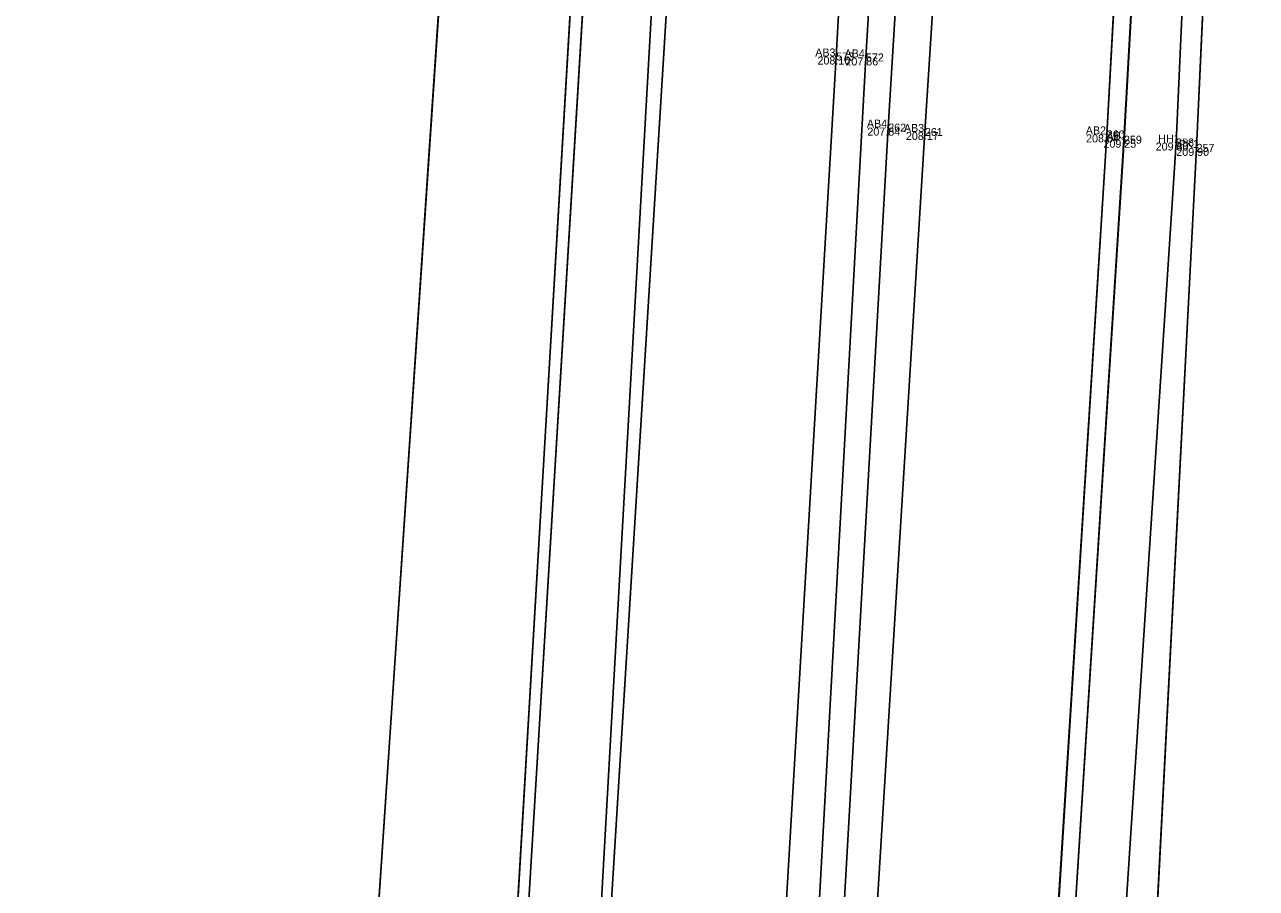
# Model space of a CAD drawing. Extents: x -263091 to -262565, y -1238731 to -1237092.
# Drawn here: x -262850.07 to -262819.29, y -1237979.18 to -1237957.59 of the extents above; entities that cross this region are included whole.
import ezdxf

# ---------------------------------------------------------------- set-up
doc = ezdxf.new("R2010")
doc.units = 0
for name, color, linetype in [('01_Hrana_betónu', 7, 'Continuous'), ('02_Oplotenie', 7, 'Continuous'), ('03_Asfalt', 7, 'Continuous'), ('05_Hrana_terénu', 7, 'Continuous'), ('09_Múrik', 7, 'Continuous'), ('Groma (21)', 7, 'Continuous'), ('Groma (22)', 7, 'Continuous'), ('Groma (23)', 7, 'Continuous'), ('Groma (24)', 7, 'Continuous'), ('U003_Asfalt', 7, 'Continuous'), ('U003_Betónové_múriky', 7, 'Continuous'), ('U003_Betónové_panely', 7, 'Continuous'), ('U003_Zeleň_mimo', 7, 'Continuous'), ('U003_Zeleň_vnútro', 7, 'Continuous'), ('U003_Zeleň_zatrávňovač', 7, 'Continuous'), ('U005_Betóny_prídavné', 7, 'Continuous')]:
    doc.layers.add(name, color=color, linetype=linetype)

msp = doc.modelspace()

# ---------------------------------------------------------------- linework, layer by layer
at = {"layer": '01_Hrana_betónu'}
for points in [[(-262903.088, -1238238.797), (-262890.817, -1238204.479), (-262885.468, -1238189.492), (-262878.003, -1238168.56), (-262870.455, -1238147.513), (-262864.947, -1238132.168), (-262859.037, -1238116.651), (-262848.977, -1238095.826), (-262842.353, -1238078.361), (-262839.446, -1238067.823), (-262836.783, -1238055.069), (-262834.905, -1238040.999), (-262833.763, -1238025.462), (-262832.297, -1238000.555), (-262831.13, -1237981.111), (-262829.791, -1237958.391), (-262828.651, -1237937.03), (-262828.571, -1237935.876)], [(-262827.762, -1237935.927), (-262827.853, -1237937.062), (-262829.049, -1237958.415), (-262830.305, -1237981.211), (-262831.433, -1238000.629), (-262832.987, -1238025.43), (-262834.086, -1238041.027), (-262836.169, -1238055.023), (-262838.684, -1238068.024), (-262841.681, -1238078.569), (-262848.285, -1238096.308), (-262858.162, -1238116.913), (-262863.876, -1238132.122), (-262869.919, -1238147.692), (-262877.244, -1238168.638), (-262884.69, -1238189.67), (-262901.991, -1238238.762)], [(-262827.034, -1237935.973), (-262827.072, -1237937.036), (-262828.491, -1237960.168), (-262829.643, -1237980.454), (-262830.754, -1238002.123), (-262832.4, -1238026.024), (-262833.369, -1238041.644), (-262835.263, -1238055.011), (-262838.048, -1238068.261), (-262841.826, -1238081.232), (-262846.645, -1238094.136), (-262857.777, -1238117.273), (-262863.292, -1238131.948), (-262884.082, -1238190.299), (-262901.352, -1238238.742)], [(-262900.376, -1238238.711), (-262890.192, -1238209.46), (-262883.463, -1238190.564), (-262868.512, -1238148.877), (-262862.514, -1238132.276), (-262857.014, -1238117.706), (-262845.846, -1238094.561), (-262841.058, -1238081.49), (-262837.218, -1238068.474), (-262834.492, -1238055.416), (-262832.606, -1238041.772), (-262831.509, -1238026.143), (-262830.024, -1238002.24), (-262828.826, -1237980.518), (-262827.576, -1237960.277), (-262826.117, -1237937.218), (-262826.079, -1237936.033)]]:
    msp.add_lwpolyline(points, dxfattribs=at)
at = {"layer": '02_Oplotenie'}
for points in [[(-262912.451, -1238238.295), (-262908.254, -1238226.663), (-262901.526, -1238207.942), (-262898.552, -1238199.602), (-262894.22, -1238186.327), (-262886.794, -1238165.648), (-262879.297, -1238144.201), (-262873.976, -1238128.814), (-262867.141, -1238113.572), (-262855.316, -1238089.931), (-262850.675, -1238078.807), (-262846.261, -1238065.654), (-262843.56, -1238054.226), (-262842.344, -1238048.099), (-262841.445, -1238040.349), (-262840.733, -1238030.077), (-262839.013, -1238000.384), (-262838.353, -1237989.712), (-262835.178, -1237935.879)], [(-262819.762, -1237938.034), (-262820.788, -1237960.675), (-262821.837, -1237980.919), (-262823.308, -1238002.106), (-262824.582, -1238026.068), (-262825.82, -1238041.973), (-262827.772, -1238056.552), (-262830.57, -1238069.546), (-262834.589, -1238083.855), (-262839.328, -1238095.835), (-262848.782, -1238120.942), (-262853.684, -1238135.175), (-262859.896, -1238152.781), (-262867.698, -1238174.329), (-262874.833, -1238193.487), (-262881.88, -1238212.036), (-262887.174, -1238225.693), (-262888.829, -1238230.138)]]:
    msp.add_lwpolyline(points, dxfattribs=at)
at = {"layer": '03_Asfalt'}
msp.add_lwpolyline([(-262912.678, -1238239.103), (-262913.356, -1238239.285), (-262915.717, -1238239.279), (-262916.328, -1238238.784), (-262916.575, -1238236.319), (-262915.768, -1238233.661), (-262912.404, -1238225.097), (-262904.805, -1238205.606), (-262896.687, -1238184.948), (-262888.478, -1238163.929), (-262880.124, -1238142.63), (-262874.65, -1238128.675), (-262868.549, -1238113.075), (-262858.861, -1238088.481), (-262853.132, -1238074.038), (-262850.084, -1238066.288), (-262845.869, -1238049.471), (-262845.094, -1238038.662), (-262844.346, -1238028.542), (-262842.599, -1238000.955), (-262841.603, -1237985.168), (-262838.824, -1237943.888), (-262838.24, -1237934.633), (-262838.283, -1237933.488)], dxfattribs=at)
at = {"layer": '05_Hrana_terénu'}
for points in [[(-262835.062, -1237935.275), (-262834.86, -1237936.333), (-262838.087, -1237989.633), (-262838.484, -1238000.332), (-262840.387, -1238030.181), (-262840.991, -1238040.253), (-262843.126, -1238054.282), (-262845.675, -1238066.436), (-262850.413, -1238079.623), (-262854.798, -1238090.209), (-262863.856, -1238108.78), (-262866.643, -1238114.502), (-262872.333, -1238129.41), (-262877.981, -1238144.625), (-262885.616, -1238166.033), (-262893.121, -1238186.676), (-262898.244, -1238201.149), (-262900.554, -1238208.001), (-262907.375, -1238226.781), (-262911.85, -1238238.364), (-262912.678, -1238239.103)], [(-262849.564, -1238120.544), (-262839.894, -1238095.583), (-262835.301, -1238083.403), (-262831.402, -1238069.334), (-262828.632, -1238056.516), (-262826.436, -1238041.83), (-262825.08, -1238026.06), (-262823.863, -1238001.967), (-262822.633, -1237980.847), (-262821.298, -1237960.54), (-262820.334, -1237939.047), (-262819.871, -1237937.657)]]:
    msp.add_lwpolyline(points, dxfattribs=at)
at = {"layer": '09_Múrik'}
for points in [[(-262845.277, -1238070.627), (-262844.218, -1238066.744), (-262841.577, -1238054.272), (-262839.647, -1238040.289), (-262838.75, -1238030.675), (-262836.979, -1238000.411), (-262836.237, -1237989.843), (-262834.391, -1237956.949), (-262833.055, -1237935.594)], [(-262844.833, -1238070.767), (-262843.906, -1238066.814), (-262841.249, -1238054.245), (-262839.306, -1238040.158), (-262838.493, -1238030.433), (-262836.614, -1238000.277), (-262836.049, -1237989.856), (-262833.996, -1237956.678), (-262832.67, -1237935.618)], [(-262840.924, -1238094.827), (-262836.941, -1238083.068), (-262832.969, -1238069.042), (-262830.214, -1238056.416), (-262828.063, -1238041.942), (-262826.83, -1238026.465), (-262825.494, -1238001.855), (-262824.316, -1237980.84), (-262823.031, -1237960.337), (-262821.719, -1237936.336)], [(-262840.6, -1238094.732), (-262836.43, -1238082.967), (-262832.633, -1238069.1), (-262829.86, -1238056.421), (-262827.688, -1238042.018), (-262826.338, -1238026.448), (-262825.108, -1238001.872), (-262823.89, -1237980.741), (-262822.602, -1237960.47), (-262821.253, -1237936.39)]]:
    msp.add_lwpolyline(points, dxfattribs=at)
at = {"layer": 'Groma (21)'}
for centre in [(-262829.791, -1237958.391), (-262829.049, -1237958.415), (-262828.491, -1237960.168), (-262827.576, -1237960.277), (-262823.031, -1237960.337), (-262822.602, -1237960.47), (-262821.298, -1237960.54), (-262820.788, -1237960.675)]:
    msp.add_circle(centre, 0.01, dxfattribs=at)
at = {"layer": 'U003_Asfalt'}
for points in [[(-262836.86, -1238089.78), (-262834.59, -1238083.86), (-262830.57, -1238069.55), (-262827.77, -1238056.55), (-262825.82, -1238041.97), (-262824.58, -1238026.07), (-262823.31, -1238002.11), (-262821.84, -1237980.92), (-262820.79, -1237960.68), (-262819.76, -1237938.03), (-262819.87, -1237937.66), (-262818.51, -1237937.77), (-262818.3, -1237934.7)], [(-262824.58, -1238026.07), (-262823.31, -1238002.11), (-262821.84, -1237980.92), (-262820.79, -1237960.68), (-262819.76, -1237938.03), (-262819.87, -1237937.66), (-262818.51, -1237937.77), (-262818.3, -1237934.7)]]:
    msp.add_lwpolyline(points, dxfattribs=at)
at = {"layer": 'U003_Betónové_múriky'}
for points in [[(-262834.39, -1237956.95), (-262833.05, -1237935.59), (-262832.67, -1237935.62), (-262834, -1237956.68), (-262836.05, -1237989.86), (-262836.61, -1238000.28), (-262838.49, -1238030.43), (-262839.31, -1238040.16), (-262841.25, -1238054.25), (-262843.91, -1238066.81), (-262844.83, -1238070.77), (-262845.28, -1238070.63), (-262844.22, -1238066.74), (-262841.58, -1238054.27), (-262839.65, -1238040.29), (-262838.75, -1238030.68), (-262836.98, -1238000.41), (-262836.24, -1237989.84)], [(-262821.25, -1237936.39), (-262822.6, -1237960.47), (-262823.89, -1237980.74), (-262825.11, -1238001.87), (-262826.34, -1238026.45), (-262827.69, -1238042.02), (-262829.86, -1238056.42), (-262832.63, -1238069.1), (-262836.43, -1238082.97), (-262840.6, -1238094.73), (-262840.92, -1238094.83), (-262836.94, -1238083.07), (-262832.97, -1238069.04), (-262830.21, -1238056.42), (-262828.06, -1238041.94), (-262826.83, -1238026.47), (-262825.49, -1238001.86), (-262824.32, -1237980.84), (-262823.03, -1237960.34), (-262821.72, -1237936.34)]]:
    msp.add_lwpolyline(points, close=True, dxfattribs=at)
for points in [[(-262836.24, -1237989.84), (-262834.39, -1237956.95), (-262833.05, -1237935.59), (-262832.67, -1237935.62), (-262834, -1237956.68), (-262836.05, -1237989.86), (-262836.61, -1238000.28), (-262838.49, -1238030.43), (-262839.31, -1238040.16), (-262841.25, -1238054.25), (-262843.91, -1238066.81), (-262844.83, -1238070.77), (-262845.28, -1238070.63), (-262844.22, -1238066.74), (-262841.58, -1238054.27), (-262839.65, -1238040.29), (-262838.75, -1238030.68), (-262836.98, -1238000.41), (-262836.24, -1237989.84)], [(-262821.72, -1237936.34), (-262821.25, -1237936.39), (-262822.6, -1237960.47), (-262823.89, -1237980.74), (-262825.11, -1238001.87), (-262826.34, -1238026.45), (-262827.69, -1238042.02), (-262829.86, -1238056.42), (-262832.63, -1238069.1), (-262836.43, -1238082.97), (-262840.6, -1238094.73), (-262840.92, -1238094.83), (-262836.94, -1238083.07), (-262832.97, -1238069.04), (-262830.21, -1238056.42), (-262828.06, -1238041.94), (-262826.83, -1238026.47), (-262825.49, -1238001.86), (-262824.32, -1237980.84), (-262823.03, -1237960.34), (-262821.72, -1237936.34)]]:
    msp.add_lwpolyline(points, dxfattribs=at)
at = {"layer": 'U003_Betónové_panely'}
for points in [[(-262863.7, -1238113.97), (-262862.86, -1238112.21), (-262862.02, -1238109.74), (-262852.53, -1238091.41), (-262847.76, -1238078.52), (-262845.51, -1238070.71), (-262845.28, -1238070.63), (-262844.83, -1238070.77), (-262843.91, -1238066.81), (-262841.25, -1238054.25), (-262839.31, -1238040.16), (-262838.49, -1238030.43), (-262836.61, -1238000.28), (-262836.05, -1237989.86), (-262834, -1237956.68), (-262832.67, -1237935.62), (-262832.64, -1237935.62), (-262832.51, -1237933.84)], [(-262863.7, -1238113.97), (-262862.86, -1238112.21), (-262862.02, -1238109.74), (-262852.53, -1238091.41), (-262847.76, -1238078.52), (-262845.51, -1238070.71), (-262845.28, -1238070.63), (-262844.83, -1238070.77), (-262843.91, -1238066.81), (-262841.25, -1238054.25), (-262839.31, -1238040.16), (-262838.49, -1238030.43), (-262836.61, -1238000.28), (-262836.05, -1237989.86), (-262834, -1237956.68), (-262832.67, -1237935.62), (-262832.64, -1237935.62), (-262832.51, -1237933.84)], [(-262822, -1237934.47), (-262822.23, -1237936.28), (-262821.72, -1237936.34), (-262823.03, -1237960.34), (-262824.32, -1237980.84), (-262825.49, -1238001.86), (-262826.83, -1238026.47), (-262828.06, -1238041.94), (-262830.21, -1238056.42), (-262832.97, -1238069.04), (-262836.94, -1238083.07), (-262840.92, -1238094.83), (-262840.6, -1238094.73), (-262841.76, -1238095.81), (-262851.46, -1238119.84), (-262857.2, -1238134.12), (-262863.32, -1238150.73), (-262871.41, -1238173.11), (-262878.16, -1238192.14), (-262884.61, -1238210.94), (-262889.86, -1238225.24), (-262892.75, -1238232.5), (-262895.19, -1238238.55), (-262900.83, -1238252.4)], [(-262822, -1237934.47), (-262822.23, -1237936.28), (-262821.72, -1237936.34), (-262823.03, -1237960.34), (-262824.32, -1237980.84), (-262825.49, -1238001.86), (-262826.83, -1238026.47), (-262828.06, -1238041.94), (-262830.21, -1238056.42), (-262832.97, -1238069.04), (-262836.94, -1238083.07), (-262840.92, -1238094.83), (-262840.6, -1238094.73), (-262841.76, -1238095.81), (-262851.46, -1238119.84), (-262857.2, -1238134.12), (-262863.32, -1238150.73), (-262871.41, -1238173.11), (-262878.16, -1238192.14), (-262884.61, -1238210.94), (-262889.86, -1238225.24), (-262892.75, -1238232.5), (-262895.19, -1238238.55), (-262900.83, -1238252.4)]]:
    msp.add_lwpolyline(points, dxfattribs=at)
at = {"layer": 'U003_Zeleň_mimo'}
for points in [[(-262868.55, -1238113.08), (-262858.86, -1238088.48), (-262853.13, -1238074.04), (-262850.08, -1238066.29), (-262845.87, -1238049.47), (-262845.09, -1238038.66), (-262844.35, -1238028.54), (-262842.6, -1238000.96), (-262841.6, -1237985.17), (-262838.82, -1237943.89), (-262838.24, -1237934.63)], [(-262836.32, -1237934.59), (-262836.29, -1237935.17), (-262835.06, -1237935.28), (-262835.18, -1237935.88), (-262838.35, -1237989.71), (-262839.01, -1238000.38), (-262840.73, -1238030.08), (-262841.45, -1238040.35), (-262842.34, -1238048.1), (-262843.56, -1238054.23), (-262846.26, -1238065.65), (-262850.68, -1238078.81), (-262855.32, -1238089.93), (-262867.14, -1238113.57)]]:
    msp.add_lwpolyline(points, dxfattribs=at)
at = {"layer": 'U003_Zeleň_vnútro'}
for points in [[(-262840.73, -1238030.08), (-262839.01, -1238000.38), (-262838.35, -1237989.71), (-262835.18, -1237935.88), (-262835.06, -1237935.28), (-262834.66, -1237935.73), (-262834.86, -1237936.33), (-262838.09, -1237989.63), (-262838.48, -1238000.33), (-262840.39, -1238030.18)], [(-262840.73, -1238030.08), (-262839.01, -1238000.38), (-262838.35, -1237989.71), (-262835.18, -1237935.88), (-262835.06, -1237935.28), (-262834.66, -1237935.73), (-262834.86, -1237936.33), (-262838.09, -1237989.63), (-262838.48, -1238000.33), (-262840.39, -1238030.18)], [(-262849.56, -1238120.54), (-262839.89, -1238095.58), (-262835.3, -1238083.4), (-262831.4, -1238069.33), (-262828.63, -1238056.52), (-262826.44, -1238041.83), (-262825.08, -1238026.06), (-262823.86, -1238001.97), (-262822.63, -1237980.85), (-262821.3, -1237960.54), (-262820.33, -1237939.05), (-262819.87, -1237937.66), (-262819.76, -1237938.03), (-262820.79, -1237960.68), (-262821.84, -1237980.92), (-262823.31, -1238002.11), (-262824.58, -1238026.07), (-262825.82, -1238041.97), (-262827.77, -1238056.55), (-262830.57, -1238069.55), (-262834.59, -1238083.86), (-262839.33, -1238095.84), (-262848.78, -1238120.94)], [(-262849.56, -1238120.54), (-262839.89, -1238095.58), (-262835.3, -1238083.4), (-262831.4, -1238069.33), (-262828.63, -1238056.52), (-262826.44, -1238041.83), (-262825.08, -1238026.06), (-262823.86, -1238001.97), (-262822.63, -1237980.85), (-262821.3, -1237960.54), (-262820.33, -1237939.05), (-262819.87, -1237937.66), (-262819.76, -1237938.03), (-262820.79, -1237960.68), (-262821.84, -1237980.92), (-262823.31, -1238002.11), (-262824.58, -1238026.07), (-262825.82, -1238041.97), (-262827.77, -1238056.55), (-262830.57, -1238069.55), (-262834.59, -1238083.86), (-262839.33, -1238095.84), (-262848.78, -1238120.94)]]:
    msp.add_lwpolyline(points, dxfattribs=at)
at = {"layer": 'U003_Zeleň_zatrávňovač'}
for points in [[(-262840.39, -1238030.18), (-262838.48, -1238000.33), (-262838.09, -1237989.63), (-262834.86, -1237936.33), (-262834.66, -1237935.73), (-262834.56, -1237935.8), (-262833.68, -1237935.77), (-262833.66, -1237935.47), (-262832.64, -1237935.62), (-262833.05, -1237935.59), (-262834.39, -1237956.95), (-262836.24, -1237989.84), (-262836.98, -1238000.41), (-262838.75, -1238030.68)], [(-262840.39, -1238030.18), (-262838.48, -1238000.33), (-262838.09, -1237989.63), (-262834.86, -1237936.33), (-262834.66, -1237935.73), (-262834.56, -1237935.8), (-262833.68, -1237935.77), (-262833.66, -1237935.47), (-262832.64, -1237935.62), (-262833.05, -1237935.59), (-262834.39, -1237956.95), (-262836.24, -1237989.84), (-262836.98, -1238000.41), (-262838.75, -1238030.68)], [(-262826.34, -1238026.45), (-262825.11, -1238001.87), (-262823.89, -1237980.74), (-262822.6, -1237960.47), (-262821.25, -1237936.39), (-262821.23, -1237936.39), (-262821.09, -1237936.69), (-262819.91, -1237936.88), (-262819.87, -1237937.66), (-262820.33, -1237939.05), (-262821.3, -1237960.54), (-262822.63, -1237980.85), (-262823.86, -1238001.97), (-262825.08, -1238026.06)]]:
    msp.add_lwpolyline(points, dxfattribs=at)
at = {"layer": 'U005_Betóny_prídavné'}
msp.add_lwpolyline([(-262826.34, -1238026.45), (-262825.11, -1238001.87), (-262823.89, -1237980.74), (-262822.6, -1237960.47), (-262821.25, -1237936.39), (-262821.23, -1237936.39), (-262821.09, -1237936.69), (-262819.91, -1237936.88), (-262819.87, -1237937.66), (-262820.33, -1237939.05), (-262821.3, -1237960.54), (-262822.63, -1237980.85), (-262823.86, -1238001.97), (-262825.08, -1238026.06)], dxfattribs=at)

# ---------------------------------------------------------------- texts
at = {"layer": 'Groma (22)'}
for s, p in [('573', (-262829.791, -1237958.491)), ('572', (-262829.049, -1237958.515)), ('262', (-262828.491, -1237960.268)), ('261', (-262827.576, -1237960.377)), ('260', (-262823.031, -1237960.437)), ('259', (-262822.602, -1237960.57)), ('258', (-262821.298, -1237960.64)), ('257', (-262820.788, -1237960.775))]:
    msp.add_text(s, height=0.2, dxfattribs=at).set_placement(p)
at = {"layer": 'Groma (23)'}
for s, p in [('208.16', (-262830.259, -1237958.591)), ('207.86', (-262829.562, -1237958.615)), ('207.84', (-262829.013, -1237960.368)), ('208.17', (-262828.05, -1237960.477)), ('208.64', (-262823.548, -1237960.537)), ('209.25', (-262823.114, -1237960.67)), ('209.80', (-262821.809, -1237960.74)), ('209.90', (-262821.294, -1237960.875))]:
    msp.add_text(s, height=0.2, dxfattribs=at).set_placement(p)
at = {"layer": 'Groma (24)'}
for s, p in [('AB3', (-262830.315, -1237958.391)), ('AB4', (-262829.583, -1237958.415)), ('AB4', (-262829.025, -1237960.168)), ('AB3', (-262828.1, -1237960.277)), ('AB2', (-262823.555, -1237960.337)), ('AB1', (-262823.04, -1237960.47)), ('HH1', (-262821.745, -1237960.54)), ('PK1', (-262821.235, -1237960.675))]:
    msp.add_text(s, height=0.2, dxfattribs=at).set_placement(p)

doc.saveas('drawing.dxf')
